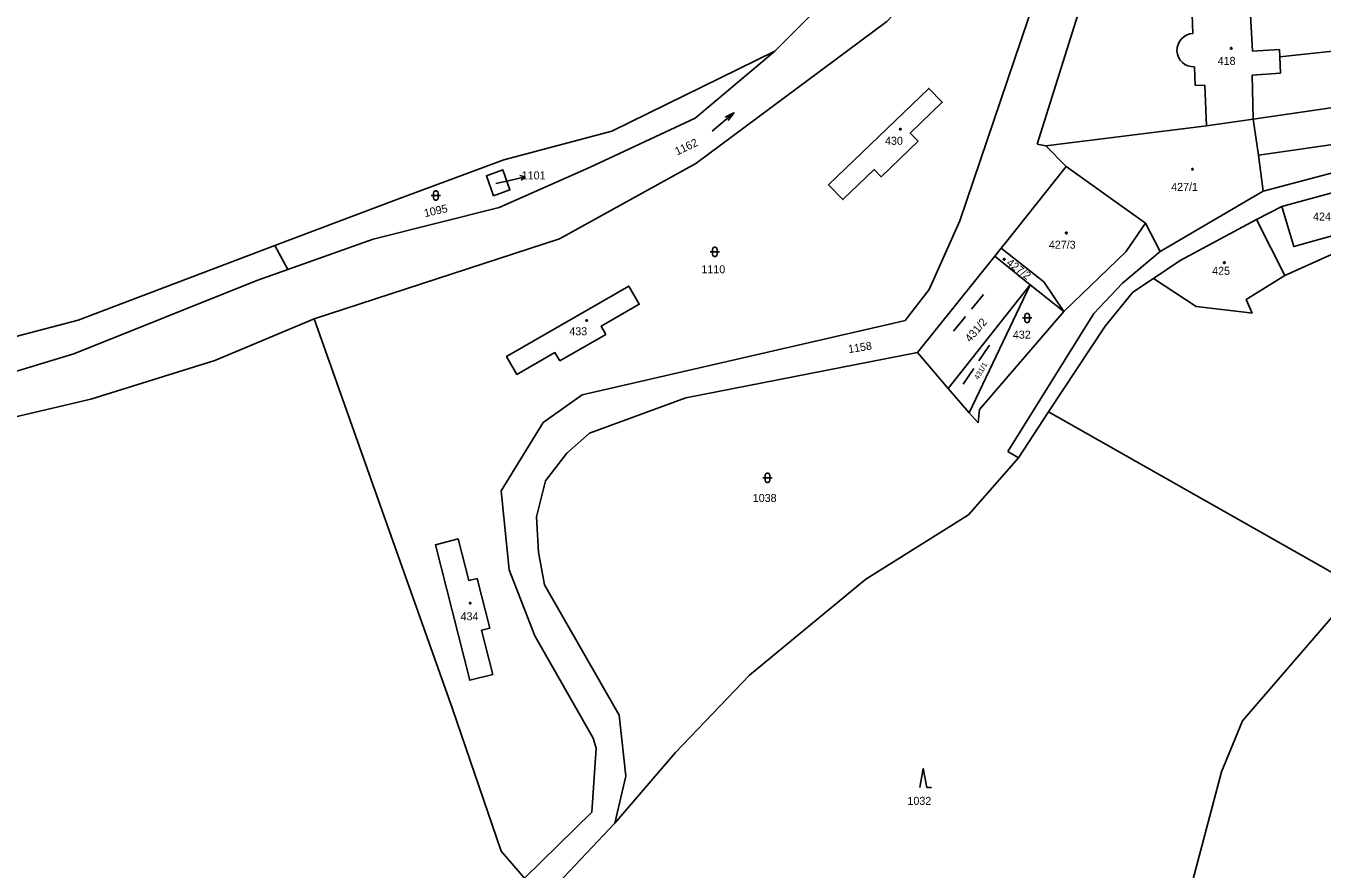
# Model space of a CAD drawing. Extents: x -812394 to -807601, y -1013097 to -1009266.
# Drawn here: x -811273.1 to -810997.7, y -1011891.6 to -1011712.3 of the extents above; entities that cross this region are included whole.
import ezdxf

# ---------------------------------------------------------------- set-up
doc = ezdxf.new("R2010")
doc.units = 0
for name, color, linetype in [('Default', 7, 'Continuous'), ('KN_HRANICE', 7, 'Continuous'), ('KN_KULTURY', 7, 'Continuous'), ('KN_PARCELY', 7, 'Continuous'), ('KN_SLUCKY', 7, 'Continuous')]:
    doc.layers.add(name, color=color, linetype=linetype)

# ---------------------------------------------------------------- blocks, each defined once
blk = doc.blocks.new('10292')
at = {"layer": 'Default'}
blk.add_line((0, 3), (0, 0), dxfattribs=at)
blk.add_lwpolyline([(-0.5, 2), (0, 3), (0.5, 2)], dxfattribs=at)
blk = doc.blocks.new('308')
at = {"layer": 'Default'}
blk.add_lwpolyline([(-0.75, 0), (0, 4), (0.75, 0), (1.75, 0)], dxfattribs=at)
blk = doc.blocks.new('316')
at = {"layer": 'Default'}
for points in [[(-1, 1), (0.27, 1), (1, 1)], [(-0.5, 1.5), (-0.4, 1.79), (-0.15, 1.97), (0.16, 1.97), (0.41, 1.79), (0.51, 1.5), (0.51, 0.5), (0.41, 0.21), (0.16, 0.03), (-0.15, 0.03), (-0.4, 0.21), (-0.5, 0.5), (-0.5, 1.5)]]:
    blk.add_lwpolyline(points, dxfattribs=at)
blk = doc.blocks.new('NAHRADNI_SYMBOL')
at = {"layer": 'Default'}
blk.add_lwpolyline([(0.09, 0.15), (0.18, 0), (0.09, -0.15), (-0.09, -0.15), (-0.18, 0), (-0.09, 0.15), (0.09, 0.15)], dxfattribs=at)
blk = doc.blocks.new('802')
at = {"layer": 'Default'}
blk.add_line((-3, 0), (3, 0), dxfattribs=at)
blk.add_lwpolyline([(1, 0.5), (3, 0), (1, -0.5)], dxfattribs=at)
blk = doc.blocks.new('803')
at = {"layer": 'Default'}
for p, q in [((-7.5, 0), (-1.5, 0)), ((1.5, 0), (7.5, 0))]:
    blk.add_line(p, q, dxfattribs=at)
blk = doc.blocks.new('402')
at = {"layer": 'Default'}
blk.add_lwpolyline([(0.09, 0.15), (0.18, 0), (0.09, -0.15), (-0.09, -0.15), (-0.18, 0), (-0.09, 0.15), (0.09, 0.15)], dxfattribs=at)

msp = doc.modelspace()

# ---------------------------------------------------------------- linework, layer by layer
at = {"layer": 'KN_HRANICE'}
for p, q in [((-811036.27, -1011667.85), (-811058.25, -1011737.49)), ((-811113.97, -1011717.72), (-811101.04, -1011704.72)), ((-811025.3, -1011710.01), (-811025.13, -1011713.95)), ((-811148.58, -1011734.71), (-811113.97, -1011717.72)), ((-811024.65, -1011724.99), (-811024.82, -1011721.05)), ((-811022.63, -1011724.91), (-811024.65, -1011724.99)), ((-811022.25, -1011733.58), (-811022.63, -1011724.91)), ((-811022.25, -1011733.58), (-811012.33, -1011732.15)), ((-811012.33, -1011732.15), (-811011.17, -1011739.82)), ((-811171.54, -1011740.78), (-811148.58, -1011734.71)), ((-811056.39, -1011737.86), (-811022.25, -1011733.58)), ((-811058.25, -1011737.49), (-811056.39, -1011737.86)), ((-811056.39, -1011737.86), (-811052.09, -1011742.26)), ((-811011.17, -1011739.82), (-811010.19, -1011747.48)), ((-811010.19, -1011747.48), (-810977.33, -1011738.74)), ((-811194.29, -1011749.24), (-811171.54, -1011740.78)), ((-811052.09, -1011742.26), (-811064.98, -1011758.48)), ((-811035.21, -1011754.31), (-811052.09, -1011742.26)), ((-811012.74, -1011748.94), (-811010.19, -1011747.48)), ((-810990.56, -1011746.41), (-811006.21, -1011750.72)), ((-811220.22, -1011759.06), (-811194.29, -1011749.24)), ((-811199.35, -1011757.68), (-811172.54, -1011750.96)), ((-811032.06, -1011760.31), (-811012.74, -1011748.94)), ((-811006.21, -1011750.72), (-811011.62, -1011753.48)), ((-811074.63, -1011753.78), (-811081.18, -1011768.41)), ((-811039.37, -1011760.37), (-811035.21, -1011754.31)), ((-811035.21, -1011754.31), (-811032.06, -1011760.31)), ((-811011.62, -1011753.48), (-811005.63, -1011765.4)), ((-811262.02, -1011774.9), (-811220.22, -1011759.06)), ((-811217.49, -1011764.12), (-811220.22, -1011759.06)), ((-811217.49, -1011764.12), (-811199.35, -1011757.68)), ((-811065.85, -1011759.58), (-811067.22, -1011761.3)), ((-811064.98, -1011758.48), (-811065.85, -1011759.58)), ((-811056.84, -1011766.74), (-811065.85, -1011759.58)), ((-811005.63, -1011765.4), (-810987.54, -1011757.25)), ((-811067.22, -1011761.3), (-811083.69, -1011781.79)), ((-811067.22, -1011761.3), (-811059.74, -1011767.4)), ((-811052.53, -1011773.05), (-811039.37, -1011760.37)), ((-811032.06, -1011760.31), (-811040.13, -1011767.06)), ((-811224.02, -1011766.44), (-811217.49, -1011764.12)), ((-811262.9, -1011782.04), (-811224.02, -1011766.44)), ((-811077.11, -1011789.44), (-811059.74, -1011767.4)), ((-811059.74, -1011767.4), (-811072.69, -1011794.59)), ((-811059.74, -1011767.4), (-811052.53, -1011773.05)), ((-811052.53, -1011773.05), (-811056.84, -1011766.74)), ((-811040.13, -1011767.06), (-811046.19, -1011773.46)), ((-811037.93, -1011768.93), (-811033.54, -1011766.01)), ((-811081.18, -1011768.41), (-811086.29, -1011774.95)), ((-811043.81, -1011776.2), (-811037.93, -1011768.93)), ((-811070.51, -1011793.88), (-811052.53, -1011773.05)), ((-811046.19, -1011773.46), (-811064.47, -1011802.81)), ((-811014.19, -1011773.19), (-811012.57, -1011773.41)), ((-811296.53, -1011783.87), (-811262.02, -1011774.9)), ((-811154.9, -1011790.75), (-811088.72, -1011775.51)), ((-811086.29, -1011774.95), (-811088.72, -1011775.51)), ((-811055.79, -1011794.38), (-811043.81, -1011776.2)), ((-811132.85, -1011791.42), (-811083.69, -1011781.79)), ((-811083.69, -1011781.79), (-811077.11, -1011789.44)), ((-811291.86, -1011790.78), (-811262.9, -1011782.04)), ((-811077.11, -1011789.44), (-811072.69, -1011794.59)), ((-811153.33, -1011798.9), (-811132.85, -1011791.42)), ((-811072.69, -1011794.59), (-811070.75, -1011796.69)), ((-811070.75, -1011796.69), (-811070.51, -1011793.88)), ((-811055.79, -1011794.38), (-811062.22, -1011804.13)), ((-810990.1, -1011831.63), (-811055.79, -1011794.38)), ((-811158.17, -1011803.18), (-811153.33, -1011798.9)), ((-811162.67, -1011809.02), (-811158.17, -1011803.18)), ((-811064.47, -1011802.81), (-811062.22, -1011804.13)), ((-811062.22, -1011804.13), (-811072.81, -1011816.28)), ((-811164.61, -1011816.73), (-811162.67, -1011809.02)), ((-811164.22, -1011824.22), (-811164.61, -1011816.73)), ((-811072.81, -1011816.28), (-811094.61, -1011829.98)), ((-811162.9, -1011831.15), (-811164.22, -1011824.22)), ((-811147.06, -1011858.89), (-811162.9, -1011831.15)), ((-811094.61, -1011829.98), (-811119.39, -1011850.37)), ((-811014.6, -1011860.1), (-810990.1, -1011831.63)), ((-811152.56, -1011863.74), (-811164.95, -1011842)), ((-811119.39, -1011850.37), (-811135.1, -1011866.8)), ((-811145.65, -1011871.81), (-811147.06, -1011858.89)), ((-811019.07, -1011870.93), (-811014.6, -1011860.1)), ((-811152.56, -1011863.74), (-811151.94, -1011865.87)), ((-811151.94, -1011865.87), (-811152.86, -1011879.52)), ((-811135.1, -1011866.8), (-811148, -1011881.85)), ((-811148, -1011881.85), (-811145.65, -1011871.81)), ((-811025.42, -1011895.01), (-811019.07, -1011870.93)), ((-811152.86, -1011879.52), (-811167.19, -1011893.49)), ((-811162.39, -1011897.16), (-811148, -1011881.85)), ((-811167.19, -1011893.49), (-811172.1, -1011887.81))]:
    msp.add_line(p, q, dxfattribs=at)
for points in [[(-811123.04, -1011735.83), (-811090.17, -1011711.42), (-811052.04, -1011671.11)], [(-811074.63, -1011753.78), (-811047.22, -1011672.77), (-811052.04, -1011671.11)], [(-811172.54, -1011750.96), (-811153.38, -1011742.41), (-811130.88, -1011731.98), (-811113.97, -1011717.72)], [(-811211.84, -1011774.62), (-811159.7, -1011757.62), (-811130.79, -1011741.59), (-811123.04, -1011735.83)], [(-811011.62, -1011753.48), (-811027.82, -1011762.22), (-811033.54, -1011766.01)], [(-811012.57, -1011773.41), (-811013.82, -1011770.52), (-811005.63, -1011765.4)], [(-811033.54, -1011766.01), (-811024.43, -1011771.98), (-811014.19, -1011773.19)], [(-811440.11, -1011849.96), (-811421.34, -1011843.71), (-811392.71, -1011835.04), (-811348.09, -1011817.52), (-811325.66, -1011813.58), (-811310.88, -1011808.15), (-811285.31, -1011797.78), (-811259.35, -1011791.72), (-811232.94, -1011783.44), (-811211.84, -1011774.62)], [(-811211.84, -1011774.62), (-811198.18, -1011813.24), (-811182.45, -1011857.53), (-811172.1, -1011887.81)], [(-811164.95, -1011842), (-811170.42, -1011827.98), (-811172.16, -1011811.18), (-811163.19, -1011796.67), (-811154.9, -1011790.75)]]:
    msp.add_lwpolyline(points, dxfattribs=at)
for points in [[(-811083.54, -1011736.84), (-811085.2, -1011735.12), (-811078.41, -1011728.58), (-811081.26, -1011725.62), (-811102.55, -1011746.13), (-811099.51, -1011749.28), (-811092.87, -1011742.88), (-811091.4, -1011744.41)], [(-811173.73, -1011748.46), (-811175.25, -1011744.2), (-811171.79, -1011742.97), (-811170.25, -1011747.2)], [(-811159.68, -1011783.56), (-811149.9, -1011777.92), (-811150.9, -1011776.18), (-811142.78, -1011771.5), (-811145, -1011767.65), (-811170.97, -1011782.61), (-811168.77, -1011786.43), (-811160.71, -1011781.78)], [(-811174.55, -1011840.37), (-811177.23, -1011829.82), (-811178.98, -1011830.26), (-811181.24, -1011821.4), (-811186.11, -1011822.64), (-811178.79, -1011851.46), (-811173.9, -1011850.21), (-811176.29, -1011840.82)]]:
    msp.add_lwpolyline(points, close=True, dxfattribs=at)
msp.add_arc((-811024.97, -1011717.5), 3.55, 92.5841, 272.416, dxfattribs=at)
at = {"layer": 'KN_PARCELY'}
msp.add_line((-811173.23, -1011745.87), (-811169.97, -1011745.11), dxfattribs=at)
at = {"layer": 'KN_SLUCKY'}
for p, q in [((-811013.26, -1011702.91), (-811012.49, -1011717.69)), ((-810956.56, -1011713.43), (-811006.65, -1011718.94)), ((-811012.49, -1011717.69), (-811006.72, -1011717.38)), ((-811006.72, -1011717.38), (-811006.65, -1011718.94)), ((-811006.65, -1011718.94), (-811006.5, -1011722.41)), ((-811006.5, -1011722.41), (-811012.56, -1011722.82)), ((-811012.56, -1011722.82), (-811012.33, -1011732.15)), ((-811012.33, -1011732.15), (-810979.82, -1011727.46)), ((-810978.44, -1011735.16), (-811011.17, -1011739.82))]:
    msp.add_line(p, q, dxfattribs=at)
msp.add_lwpolyline([(-811006.21, -1011750.72), (-811003.67, -1011759.26), (-810988.18, -1011754.95)], dxfattribs=at)

# ---------------------------------------------------------------- block references
at = {"layer": 'KN_KULTURY'}
for name, p in [('402', (-811017, -1011717.11)), ('NAHRADNI_SYMBOL', (-811087.3, -1011734.32)), ('NAHRADNI_SYMBOL', (-811025.21, -1011742.82)), ('316', (-811186, -1011749.4)), ('NAHRADNI_SYMBOL', (-811052.04, -1011756.37)), ('316', (-811126.72, -1011761.38)), ('NAHRADNI_SYMBOL', (-811065.24, -1011761.97)), ('NAHRADNI_SYMBOL', (-811018.46, -1011762.68)), ('316', (-811060.35, -1011775.43)), ('NAHRADNI_SYMBOL', (-811153.97, -1011774.97)), ('316', (-811115.55, -1011809.42)), ('NAHRADNI_SYMBOL', (-811178.7, -1011835.04)), ('308', (-811082.43, -1011874.22))]:
    msp.add_blockref(name, p, dxfattribs=at)
at = {"layer": 'KN_KULTURY', "rotation": 40.221637}
msp.add_blockref('802', (-811124.97, -1011732.75), dxfattribs=at)
at = {"layer": 'KN_KULTURY', "xscale": 0.67}
for p, yscale, rotation in [((-811072.82, -1011773.33), 0.6699999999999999, 50.706765), ((-811071.16, -1011784.36), 0.67, 56.092568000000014)]:
    msp.add_blockref('803', p, dxfattribs=dict(at, yscale=yscale, rotation=rotation))
at = {"layer": 'KN_PARCELY', "rotation": -76.95884900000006}
msp.add_blockref('10292', (-811169.97, -1011745.11), dxfattribs=at)

# ---------------------------------------------------------------- texts
at = {"layer": 'KN_PARCELY'}
for s, height, p in [('418', 1.7, (-811019.87, -1011720.63)), ('430', 1.7, (-811090.56, -1011737.62)), ('1101', 1.7, (-811167.75, -1011744.97)), ('1101', 0.1, (-811172.93, -1011745.76)), ('427/1', 1.7, (-811029.75, -1011747.41)), ('424', 1.7, (-810999.61, -1011753.73)), ('427/3', 1.7, (-811055.74, -1011759.71)), ('1110', 1.7, (-811129.57, -1011764.93)), ('425', 1.7, (-811021.05, -1011765.25)), ('433', 1.7, (-811157.64, -1011778.11)), ('432', 1.7, (-811063.39, -1011778.83)), ('1038', 1.7, (-811118.66, -1011813.54)), ('434', 1.7, (-811180.75, -1011838.71)), ('1032', 1.7, (-811085.79, -1011877.93))]:
    msp.add_text(s, height=height, dxfattribs=at).set_placement(p)
for s, height, rotation, p in [('1162', 1.7, 25.21, (-811134.72, -1011739.89)), ('1095', 1.7, 12.834, (-811188.31, -1011753.02)), ('427/2', 1.7, 323.148, (-811064.91, -1011763.01)), ('431/2', 1.7, 49.389, (-811072.45, -1011779.7)), ('1158', 1.7, 8.881, (-811098.25, -1011781.91)), ('431/1', 1.14, 60.103, (-811070.72, -1011787.68))]:
    msp.add_text(s, height=height, rotation=rotation, dxfattribs=at).set_placement(p)

doc.saveas('drawing.dxf')
